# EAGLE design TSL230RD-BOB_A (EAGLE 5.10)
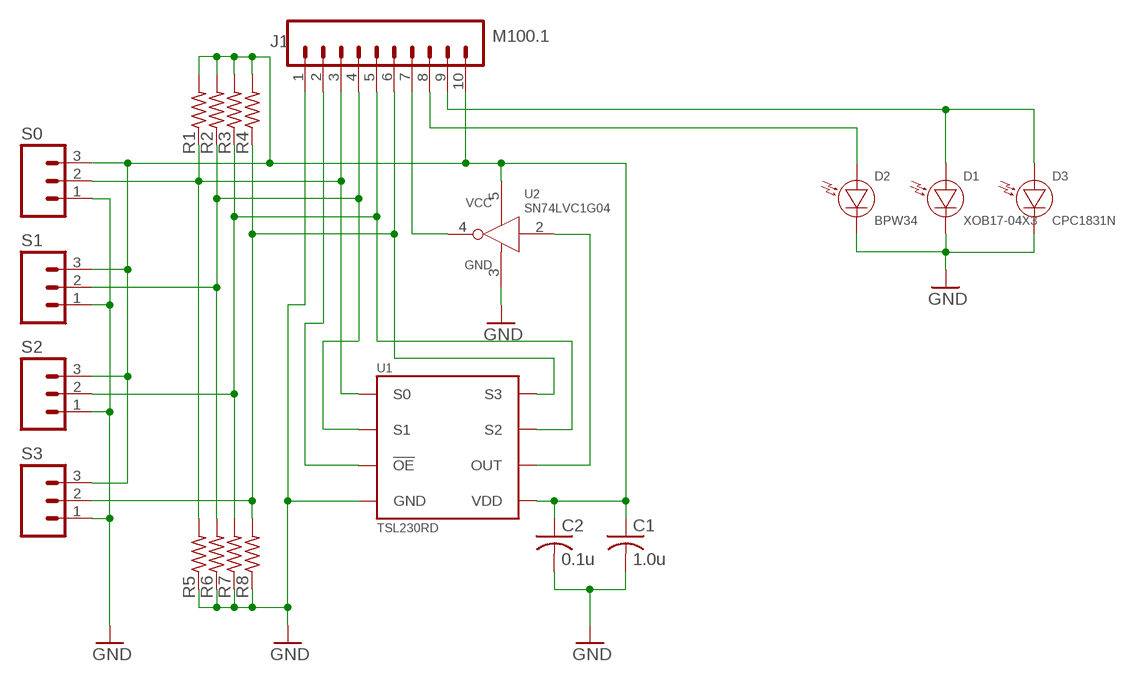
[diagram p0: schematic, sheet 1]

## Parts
C1  1.0u  C-USC0603  [C0603]
C2  0.1u  C-USC0603  [C0603]
D1  XOB17-04X3  [XOB17-04X3]
D2  BPW34  [BPW34]
D3  CPC1831N  [SOIC-8]
J1  M100.1  [1X10]
R1  R-US_R0603  [R0603]
R2  R-US_R0603  [R0603]
R3  R-US_R0603  [R0603]
R4  R-US_R0603  [R0603]
R5  R-US_R0603  [R0603]
R6  R-US_R0603  [R0603]
R7  R-US_R0603  [R0603]
R8  R-US_R0603  [R0603]
S0  M03PTH  [1X03]
S1  M03PTH  [1X03]
S2  M03PTH  [1X03]
S3  M03PTH  [1X03]
U1  TSL230RD  [TSL230RD]
U2  SN74LVC1G04  [SOT23-5]

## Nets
GND: C1.2 C2.2 D1.-(C) D2.C D3.5(C) J1.1 R5.1 R6.1 R7.1 R8.1 S0.1 S1.1 S2.1 S3.1 U1.4(GND) U2.3(GND)
N$1: D1.+(A) D3.8(A) J1.9
N$2: J1.3 R1.1 R5.2 S0.2 U1.1(S0)
N$3: J1.4 R2.1 R6.2 S1.2 U1.2(S1)
N$4: J1.5 R3.1 R7.2 S2.2 U1.7(S2)
N$5: J1.6 R4.1 R8.2 S3.2 U1.8(S3)
N$6: J1.2 U1.3(!OE)
N$7: U1.6(OUT) U2.2(A)
N$9: D2.A J1.8
N$10: J1.7 U2.4(Y)
VCC: C1.1 C2.1 J1.10 R1.2 R2.2 R3.2 R4.2 S0.3 S1.3 S2.3 S3.3 U1.5(VDD) U2.5(VCC)

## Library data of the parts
C1 C2 = rcl:C-US: CAPACITOR, American symbol
D1 = umich:XOB17-04X3
D2 = umich:BPW34
D3 = umich:CPC1831N
J1 = umich:M10: Header 10 Standard 10-pin 0.1" header. Use with straight break away headers (SKU : PRT-00116), right angle break away headers (PRT-00553), swiss pins (PRT-00743), machine pins (PRT-00117), and female headers (PRT-00115).
R1-R8 = rcl:R-US_: RESISTOR, American symbol
S0 S1-S3 = umich:M03: Header 3 Standard 3-pin 0.1" header. Use with straight break away headers (SKU : PRT-00116), right angle break away headers (PRT-00553), swiss pins (PRT-00743), machine pins (PRT-00117), and female headers (PRT-00115). Molex polarized connector foot print use with SKU : PRT-08232 with associated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
U1 = umich:TSL230RD
U2 = umich:SN74LVC1G04

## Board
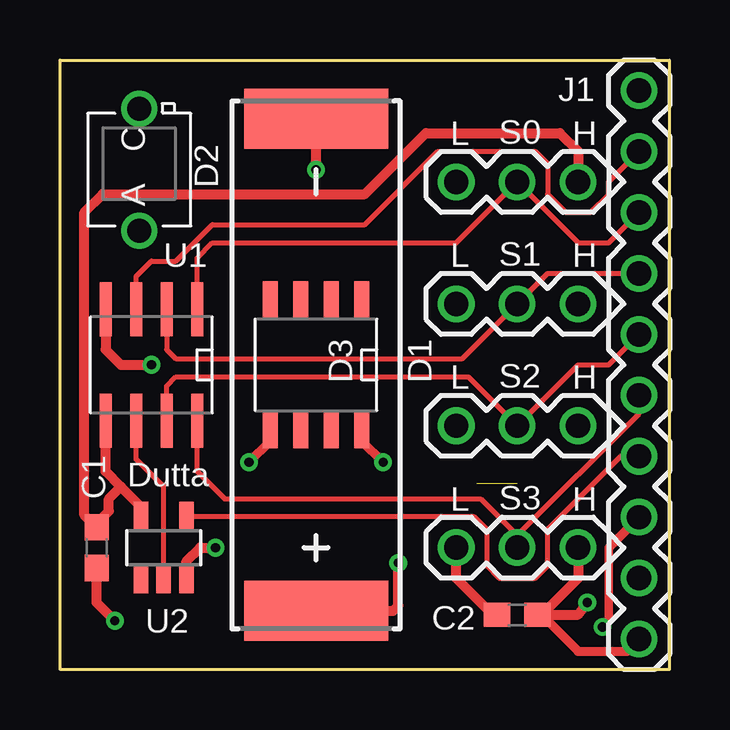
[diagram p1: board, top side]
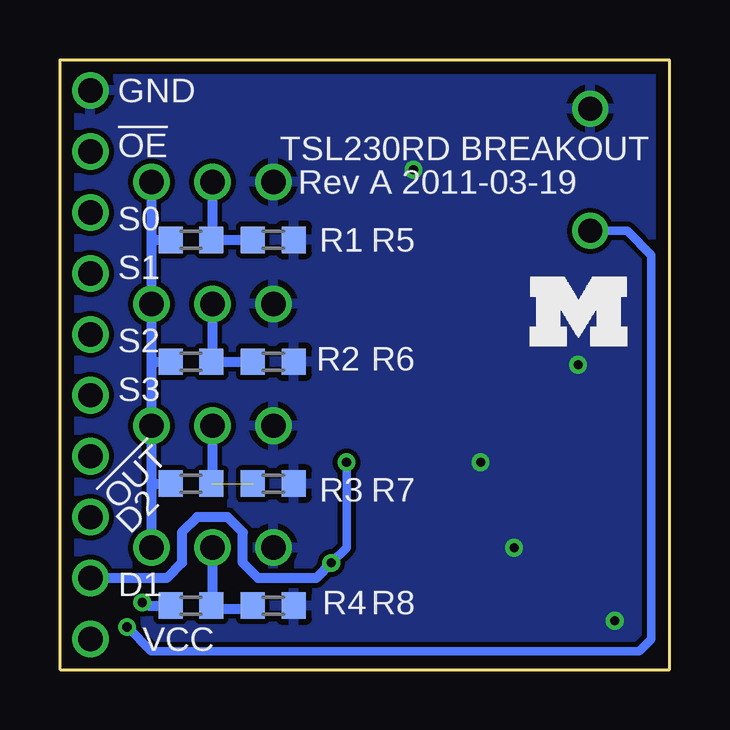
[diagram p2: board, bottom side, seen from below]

Size 25.4 x 25.4 mm. Coordinates in mm from the lower left corner, seen from the top.
Outline: 25.4,0 25.4,25.4 0,25.4 0,0 25.4,0
Copper layers (1*16): Top 0.035mm / dielectric 1.5mm / Bottom 0.035mm
Design rules "default *": minimum track width 8mil, minimum drill 12mil, track to track 8mil, track to pad 8mil, pad to pad 8mil, via to via 8mil, smd to smd 8mil, copper to edge 20mil, drill to drill 8mil, minimum pad ring 7mil, minimum via ring 7mil, stop-mask expansion 4mil, vias tented up to drill 0mil, thermal gap 10mil

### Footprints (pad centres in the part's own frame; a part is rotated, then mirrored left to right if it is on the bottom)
C0603 = smd 1.1 x 1: 1 -0.85,0; 2 0.85,0
XOB17-04X3 = smd 2.5 x 6: + -10.25,0; - 10.25,0
BPW34 = drill 1 pad 1.422 round: A -2.55,0; C 2.55,0
SOIC-8 = smd 0.61 x 1.549: 1 -1.905,-2.705; 2 -0.635,-2.705; 3 0.635,-2.705; 4 1.905,-2.705; 5 1.905,2.705; 6 0.635,2.705; 7 -0.635,2.705; 8 -1.905,2.705
1X10 = drill 1.016 round: 1 -11.43,0; 2 -8.89,0; 3 -6.35,0; 4 -3.81,0; 5 -1.27,0; 6 1.27,0; 7 3.81,0; 8 6.35,0; 9 8.89,0; 10 11.43,0
R0603 = smd 1 x 1.1: 1 -0.85,0; 2 0.85,0
1X03 = drill 1.016 round: 1 -2.54,0; 2 0,0; 3 2.54,0
TSL230RD = smd 0.5 x 2.25: 1 -1.905,-2.325; 2 -0.635,-2.325; 3 0.635,-2.325; 4 1.905,-2.325; 5 1.905,2.325; 6 0.635,2.325; 7 -0.635,2.325; 8 -1.905,2.325
SOT23-5 = smd 0.6 x 1.2: 1 -0.95,-1.306; 2 0,-1.306; 3 0.95,-1.306; 4 0.95,1.306; 5 -0.95,1.306

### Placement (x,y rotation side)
C1  1.52,5.08 270 top
C2  19.05,2.29 180 top
D1  10.67,12.7 90 top
D2  3.3,20.83 90 top
D3  10.67,12.7 180 top
J1  24.13,12.7 270 top
R1  19.94,17.91 180 bottom
R2  19.94,12.83 180 bottom
R3  19.94,7.75 180 bottom
R4  19.94,2.67 180 bottom
R5  16.51,17.91 180 bottom
R6  16.51,12.83 180 bottom
R7  16.51,7.75 180 bottom
R8  16.51,2.67 180 bottom
S0  19.05,20.32 0 top
S1  19.05,15.24 0 top
S2  19.05,10.16 0 top
S3  19.05,5.08 0 top
U1  3.81,12.7 180 top
U2  4.32,5.08 0 top
U$1  [BLOCK-M]  5.84,13.46 0 bottom

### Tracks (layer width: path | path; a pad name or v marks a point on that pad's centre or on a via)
GND  (via drill 0.38)
  Top 0.356: D3.5 8.76,9.53 v7.87,8.64
  Top 0.406: C2.2 18.03,2.29 16.51,3.81 S3.1 | U1.4 1.91,13.34 2.54,12.7 v3.81,12.7 | U2.3 5.27,4.51 5.84,5.08 v6.48,5.08 | v10.67,20.83 D1.- | v2.29,2.03 1.52,2.79 C1.2
  pour Bottom: 0,25.4 0,0 25.4,0 25.4,25.4
N$1  (via drill 0.38)
  Top 0.356: D3.8 12.57,9.53 v13.46,8.64
  Top 0.406: D1.+ 13.88,2.45 14.1,2.67 v14.1,4.45
  Bottom 0.356: v13.46,8.64 13.46,5.08 v14.1,4.45
  Bottom 0.406: v14.1,4.45 14.73,3.81 17.14,3.81 17.78,4.45 17.78,5.71 18.41,6.35 19.68,6.35 20.32,5.71 20.32,4.45 20.95,3.81 J1.9
N$2
  Top 0.203: U1.1 5.71,17.14 6.35,17.78 16.51,17.78 S0.2 21.59,17.78 22.86,17.78 J1.3
  Bottom 0.406: R5.2 R1.1 19.05,17.91 S0.2
N$3
  Top 0.203: U1.2 4.45,13.34 4.83,12.95 16.76,12.95 S1.2 20.32,16.51 J1.4
  Bottom 0.406: S1.2 19.05,12.83 R2.1 R6.2
N$4  (1 unrouted)
  Top 0.203: U1.7 4.45,11.81 4.83,12.19 17.02,12.19 S2.2 21.59,12.7 22.86,12.7 J1.5
  Bottom 0.406: R3.1 19.05,7.75 S2.2
N$5
  Top 0.203: U1.8 5.71,8.26 6.86,7.11 17.53,7.11 19.05,5.59 24.13,10.67 J1.6
  Top 0.406: 19.05,5.59 S3.2
  Bottom 0.406: S3.2 19.05,2.67 R4.1 18.96,2.54 17.14,2.54 17.27,2.67 R8.2
N$6
  Top 0.203: J1.2 22.86,20.32 22.86,19.81 22.1,19.05 21.08,19.05 20.32,19.81 20.32,21.08 19.81,21.59 15.75,21.59 12.7,18.54 6.35,18.54 4.83,17.02 3.81,17.02 3.17,16.38 U1.3
N$7
  Top 0.203: U1.6 3.17,8.76 4.32,7.62 U2.2
N$9  (via drill 0.38)
  Top 0.356: v22.61,1.78 22.86,2.03 22.86,5.08 J1.8
  Bottom 0.356: D2.A 1.77,18.28 0.76,17.27 0.76,1.27 1.27,0.76 21.59,0.76 v22.61,1.78
N$10
  Top 0.203: U2.4 17.24,6.39 17.78,5.84 17.78,4.32 18.29,3.81 19.81,3.81 20.32,4.32 20.32,5.84 23.37,8.89 J1.7
VCC  (via drill 0.38)
  Top 0.381: 20.07,2.29 21.59,0.76 23.62,0.76 J1.10
  Top 0.406: U1.5 1.91,8.26 2.54,7.62 | 2.54,7.62 3.37,6.79 U2.5 3.33,6.6 | 20.07,2.29 C2.1 19.9,2.12 20.07,2.29 | 20.07,2.29 21.59,3.81 S3.3 | S0.3 21.59,21.59 20.83,22.35 15.24,22.35 12.7,19.81 1.78,19.81 1.02,19.05 1.02,6.44 C1.1 1.36,5.93 2.03,6.6 2.03,7.11 2.54,7.62 | 20.07,2.29 21.59,2.29 v21.97,2.79
  Bottom 0.406: S0.3 21.59,17.91 | 21.59,12.83 S1.3 21.59,17.91 | 21.59,7.75 S2.3 21.59,12.83 | 21.59,17.91 R1.2 | 21.59,12.83 R2.2 | 21.59,7.75 R3.2 | 21.59,7.75 S3.3 | R4.2 21.72,2.67 v21.97,2.79

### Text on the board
tPlace: C | L | H | A | L | H | L | H | Dutta | L | H
bPlace: GND | TSL230RD BREAKOUT | !OE | Rev A 2011-03-19 | S0 | S1 | S2 | S3 | !OUT | D2 | D1 | VCC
